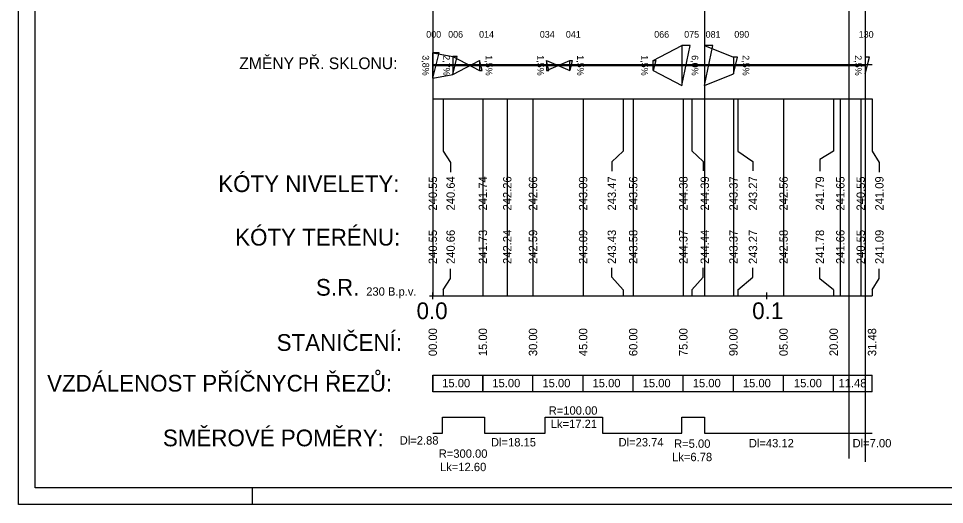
# Model space of a CAD drawing. Extents: x -598463 to -597973, y -1203201 to -1202904.
# Drawn here: x -598463.2 to -598186, y -1203201.3 to -1203056 of the extents above; entities that cross this region are included whole.
import ezdxf

# ---------------------------------------------------------------- set-up
doc = ezdxf.new("R2010")
doc.units = 0
for name, color, linetype in [('geom_osa_popis', 7, 'Continuous'), ('geom_Pomoc', 7, 'Continuous'), ('profil_popis', 7, 'Continuous'), ('profil_popis_klopeni', 7, 'Continuous'), ('profil_popis_navrh', 7, 'Continuous'), ('profil_popis_niveleta', 7, 'Continuous'), ('profil_popis_osy', 7, 'Continuous'), ('profil_popis_teren', 7, 'Continuous'), ('sil_ramecek', 7, 'Continuous')]:
    doc.layers.add(name, color=color, linetype=linetype)

msp = doc.modelspace()

# ---------------------------------------------------------------- linework, layer by layer
at = {"layer": 'geom_Pomoc'}
for p, q in [((-598339.21, -1202935.14), (-598339.21, -1203138.85)), ((-598214.71, -1202935.14), (-598214.71, -1203187.52)), ((-598257.88, -1202997.03), (-598257.88, -1203138.85)), ((-598209.75, -1203028.31), (-598209.75, -1203188.52)), ((-598339.21, -1203069.69), (-598207.73, -1203069.69)), ((-598339.21, -1203079.99), (-598207.73, -1203079.99))]:
    msp.add_line(p, q, dxfattribs=at)
at = {"layer": 'profil_popis'}
for p, q in [((-598336.05, -1203079.99), (-598336.05, -1203095.61)), ((-598316.92, -1203079.99), (-598316.92, -1203138.85)), ((-598282.26, -1203079.99), (-598282.26, -1203095.61)), ((-598261.63, -1203079.99), (-598261.63, -1203095.55)), ((-598247.91, -1203079.99), (-598247.91, -1203095.61)), ((-598217.22, -1203079.99), (-598217.22, -1203138.85)), ((-598211.12, -1203079.99), (-598211.12, -1203138.85)), ((-598336.05, -1203137.12), (-598336.05, -1203138.85)), ((-598282.26, -1203137.12), (-598282.26, -1203138.85)), ((-598261.63, -1203137.12), (-598261.63, -1203138.85)), ((-598247.91, -1203137.12), (-598247.91, -1203138.85)), ((-598339.21, -1203162.62), (-598339.21, -1203167.24)), ((-598324.21, -1203162.62), (-598324.21, -1203167.24))]:
    msp.add_line(p, q, dxfattribs=at)
for points in [[(-598339.21, -1203079.99), (-598339.21, -1203083.85), (-598339.21, -1203093.85), (-598339.21, -1203138.85)], [(-598324.21, -1203079.99), (-598324.21, -1203083.85), (-598324.21, -1203093.85), (-598324.21, -1203138.85)], [(-598309.21, -1203079.99), (-598309.21, -1203083.85), (-598309.21, -1203093.85), (-598309.21, -1203138.85)], [(-598294.21, -1203079.99), (-598294.21, -1203083.85), (-598294.21, -1203093.85), (-598294.21, -1203138.85)], [(-598279.21, -1203079.99), (-598279.21, -1203083.85), (-598279.21, -1203093.85), (-598279.21, -1203138.85)], [(-598264.21, -1203079.99), (-598264.21, -1203083.85), (-598264.21, -1203093.85), (-598264.21, -1203138.85)], [(-598249.21, -1203079.99), (-598249.21, -1203083.85), (-598249.21, -1203093.85), (-598249.21, -1203138.85)], [(-598234.21, -1203079.99), (-598234.21, -1203083.85), (-598234.21, -1203093.85), (-598234.21, -1203138.85)], [(-598219.21, -1203079.99), (-598219.21, -1203083.85), (-598219.21, -1203093.85), (-598219.21, -1203095.61)], [(-598207.73, -1203079.99), (-598207.73, -1203083.85), (-598207.73, -1203093.85), (-598207.73, -1203095.61)], [(-598336.05, -1203095.61), (-598333.86, -1203099.05), (-598333.86, -1203101.91)], [(-598282.26, -1203095.61), (-598285.62, -1203098.8), (-598285.62, -1203101.6)], [(-598261.63, -1203095.55), (-598258.28, -1203098.74), (-598258.28, -1203101.54)], [(-598247.91, -1203095.61), (-598243.37, -1203098.74), (-598243.37, -1203101.54)], [(-598219.21, -1203095.61), (-598223.33, -1203098.14), (-598223.33, -1203101.6)], [(-598207.73, -1203095.61), (-598205.54, -1203099.05), (-598205.54, -1203101.91)], [(-598336.05, -1203137.12), (-598333.86, -1203133.67), (-598333.86, -1203130.82)], [(-598282.26, -1203137.12), (-598285.62, -1203133.32), (-598285.62, -1203130.52)], [(-598261.63, -1203137.12), (-598258.28, -1203133.28), (-598258.28, -1203130.48)], [(-598247.91, -1203137.12), (-598243.37, -1203133.28), (-598243.37, -1203130.48)], [(-598219.21, -1203137.12), (-598223.33, -1203133.83), (-598223.33, -1203130.38)], [(-598207.73, -1203137.12), (-598205.54, -1203133.67), (-598205.54, -1203130.82)], [(-598219.21, -1203137.12), (-598219.21, -1203138.85)], [(-598207.73, -1203137.12), (-598207.73, -1203138.85)]]:
    msp.add_lwpolyline(points, dxfattribs=at)
at = {"layer": 'profil_popis_klopeni'}
for p, q in [((-598273.21, -1203068.49), (-598264.64, -1203063.99)), ((-598257.85, -1203063.99), (-598249.21, -1203067.49)), ((-598339.21, -1203066.19), (-598333.21, -1203067.29)), ((-598339.21, -1203073.79), (-598339.21, -1203066.19)), ((-598339.21, -1203069.99), (-598257.85, -1203069.99)), ((-598333.21, -1203072.69), (-598325.21, -1203068.49)), ((-598305.21, -1203068.49), (-598298.21, -1203071.49)), ((-598305.21, -1203071.49), (-598298.21, -1203068.49)), ((-598257.85, -1203069.99), (-598214.71, -1203069.99)), ((-598214.71, -1203069.99), (-598209.75, -1203069.99)), ((-598339.21, -1203073.79), (-598333.21, -1203072.69)), ((-598273.21, -1203071.49), (-598264.63, -1203075.99)), ((-598257.85, -1203075.99), (-598249.21, -1203072.49))]:
    msp.add_line(p, q, dxfattribs=at)
for points in [[(-598264.64, -1203063.99), (-598264.63, -1203075.99), (-598262.14, -1203063.99)], [(-598257.85, -1203063.99), (-598257.84, -1203075.99), (-598255.35, -1203063.99)], [(-598339.21, -1203066.19), (-598339.21, -1203073.79), (-598337.31, -1203066.19)], [(-598333.21, -1203067.29), (-598333.21, -1203072.69), (-598331.86, -1203067.29)], [(-598325.21, -1203068.49), (-598325.21, -1203071.49), (-598324.46, -1203071.49)], [(-598305.21, -1203068.49), (-598305.21, -1203071.49), (-598304.46, -1203071.49)], [(-598298.21, -1203071.49), (-598298.21, -1203068.49), (-598297.46, -1203068.49)], [(-598273.21, -1203071.49), (-598273.21, -1203068.49), (-598272.46, -1203068.49)], [(-598249.21, -1203067.49), (-598249.21, -1203072.49), (-598247.96, -1203067.49)], [(-598209.75, -1203067.49), (-598209.75, -1203072.49), (-598208.5, -1203067.49)]]:
    msp.add_lwpolyline(points, close=True, dxfattribs=at)
msp.add_lwpolyline([(-598333.21, -1203067.29), (-598325.21, -1203071.49), (-598325.21, -1203071.49)], dxfattribs=at)
at = {"layer": 'profil_popis_navrh'}
for points in [[(-598339.21, -1203179.98), (-598336.33, -1203179.98), (-598336.33, -1203175.18), (-598323.73, -1203175.18), (-598323.73, -1203179.98), (-598305.58, -1203179.98), (-598305.58, -1203175.18), (-598288.37, -1203175.18), (-598288.37, -1203179.98), (-598264.63, -1203179.98), (-598264.63, -1203175.18), (-598257.85, -1203175.18), (-598257.85, -1203179.98)], [(-598257.85, -1203179.98), (-598214.71, -1203179.98)], [(-598214.71, -1203179.98), (-598207.73, -1203179.98)]]:
    msp.add_lwpolyline(points, dxfattribs=at)
at = {"layer": 'profil_popis_osy'}
for p, q in [((-598340.21, -1203138.85), (-598338.21, -1203138.85)), ((-598339.21, -1203139.85), (-598339.21, -1203137.85)), ((-598339.21, -1203138.85), (-598207.73, -1203138.85)), ((-598239.21, -1203139.85), (-598239.21, -1203137.85))]:
    msp.add_line(p, q, dxfattribs=at)
at = {"layer": 'sil_ramecek'}
for p, q in [((-598339.21, -1203167.61), (-598339.21, -1203162.61)), ((-598339.21, -1203162.61), (-598207.73, -1203162.61)), ((-598324.21, -1203167.61), (-598324.21, -1203162.61)), ((-598309.21, -1203167.61), (-598309.21, -1203162.61)), ((-598294.21, -1203167.61), (-598294.21, -1203162.61)), ((-598279.21, -1203167.61), (-598279.21, -1203162.61)), ((-598264.21, -1203167.61), (-598264.21, -1203162.61)), ((-598249.21, -1203167.61), (-598249.21, -1203162.61)), ((-598234.21, -1203167.61), (-598234.21, -1203162.61)), ((-598219.21, -1203167.61), (-598219.21, -1203162.61)), ((-598207.73, -1203167.61), (-598207.73, -1203162.61)), ((-598207.73, -1203167.61), (-598339.21, -1203167.61)), ((-598393.21, -1203201.29), (-598393.21, -1203196.29))]:
    msp.add_line(p, q, dxfattribs=at)
for points in [[(-598463.21, -1202904.29), (-597973.21, -1202904.29), (-597973.21, -1203201.29), (-598463.21, -1203201.29)], [(-598458.21, -1202909.29), (-597978.21, -1202909.29), (-597978.21, -1203196.29), (-598458.21, -1203196.29)]]:
    msp.add_lwpolyline(points, close=True, dxfattribs=at)

# ---------------------------------------------------------------- texts
at = {"layer": 'geom_osa_popis'}
msp.add_text('-', height=0.0001, rotation=360, dxfattribs=at).set_placement((-598339.21, -1203138.85))
at = {"layer": 'profil_popis'}
for s, height, rotation, p in [(' KÓTY TERÉNU: ', 5, 360, (-598400.22, -1203123.85)), ('S.R.', 5, 360, (-598374.19, -1203138.85)), ('230 B.p.v.', 2.5, 360, (-598359.13, -1203138.85)), ('0.0', 5, 360, (-598344.06, -1203145.85)), ('0.1', 5, 360, (-598243.59, -1203145.85)), (' STANIČENÍ: ', 5, 360, (-598387.8, -1203155.35)), ('00.00', 2.5, 90, (-598337.96, -1203156.92)), ('15.00', 2.5, 90, (-598322.96, -1203156.92)), ('30.00', 2.5, 90, (-598307.96, -1203156.92)), ('45.00', 2.5, 90, (-598292.96, -1203156.92)), ('60.00', 2.5, 90, (-598277.96, -1203156.92)), ('75.00', 2.5, 90, (-598262.96, -1203156.92)), ('90.00', 2.5, 90, (-598247.96, -1203156.92)), ('05.00', 2.5, 90, (-598232.96, -1203156.92)), ('20.00', 2.5, 90, (-598217.96, -1203156.92)), ('31.48', 2.5, 90, (-598206.48, -1203156.93)), (' VZDÁLENOST PŘÍČNYCH ŘEZŮ: ', 5, 360, (-598456.51, -1203167.52)), ('15.00', 2.5, 360, (-598336.38, -1203166.24)), ('15.00', 2.5, 360, (-598321.38, -1203166.24)), ('15.00', 2.5, 360, (-598306.38, -1203166.24)), ('15.00', 2.5, 360, (-598291.38, -1203166.24)), ('15.00', 2.5, 360, (-598276.38, -1203166.24)), ('15.00', 2.5, 360, (-598261.38, -1203166.24)), ('15.00', 2.5, 360, (-598246.38, -1203166.24)), ('15.00', 2.5, 360, (-598231.09, -1203166.24)), ('11.48', 2.5, 360, (-598217.75, -1203166.24))]:
    msp.add_text(s, height=height, rotation=rotation, dxfattribs=at).set_placement(p)
at = {"layer": 'profil_popis_klopeni'}
for s, rotation, p in [('000', 360, (-598341.17, -1203061.7)), ('006', 360, (-598334.61, -1203061.7)), ('014', 360, (-598325.35, -1203061.7)), ('034', 360, (-598307.17, -1203061.7)), ('041', 360, (-598299.37, -1203061.7)), ('066', 360, (-598272.93, -1203061.7)), ('075', 360, (-598263.95, -1203061.7)), ('081', 360, (-598257.53, -1203061.7)), ('090', 360, (-598248.95, -1203061.7)), ('130', 360, (-598211.71, -1203061.7)), ('3,8%', 270, (-598342.3, -1203066.93)), ('2,7%', 270, (-598336.07, -1203066.93)), ('1,5%', 270, (-598323.38, -1203066.93)), ('1,5%', 270, (-598307.93, -1203066.93)), ('1,5%', 270, (-598296, -1203066.93)), ('1,5%', 270, (-598276.76, -1203066.93)), ('6,0%', 270, (-598261.72, -1203066.93)), ('2,5%', 270, (-598246.46, -1203066.93)), ('2,5%', 270, (-598212.83, -1203066.93))]:
    msp.add_text(s, height=2, rotation=rotation, dxfattribs=at).set_placement(p)
at = {"layer": 'profil_popis_navrh'}
for s, height, p in [('ZMĚNY PŘ. SKLONU: ', 3.5, (-598397.12, -1203071.09)), (' KÓTY NIVELETY: ', 5, (-598405.28, -1203107.85)), ('R=100.00', 2.5, (-598304.51, -1203174.43)), (' SMĚROVÉ POMĚRY: ', 5, (-598421.85, -1203183.89)), ('Lk=17.21', 2.5, (-598303.89, -1203178.43)), ('Dl=2.88', 2.5, (-598349.11, -1203183.38)), ('Dl=18.15', 2.5, (-598321.79, -1203183.93)), ('Dl=23.74', 2.5, (-598283.6, -1203183.93)), ('R=5.00', 2.5, (-598266.98, -1203184.34)), ('Dl=43.12', 2.5, (-598244.6, -1203184.21)), ('Dl=7.00', 2.5, (-598213.55, -1203184.21)), ('R=300.00', 2.5, (-598337.43, -1203187.32)), ('Lk=6.78', 2.5, (-598267.57, -1203188.34)), ('Lk=12.60', 2.5, (-598337.04, -1203191.32))]:
    msp.add_text(s, height=height, rotation=360, dxfattribs=at).set_placement(p)
at = {"layer": 'profil_popis_niveleta'}
for s, p in [('240.55', (-598337.96, -1203113.39)), ('240.64', (-598332.61, -1203113.36)), ('241.74', (-598322.96, -1203113.36)), ('242.26', (-598315.67, -1203113.37)), ('242.66', (-598307.96, -1203113.37)), ('243.09', (-598292.96, -1203113.37)), ('243.47', (-598284.37, -1203113.37)), ('243.56', (-598277.96, -1203113.37)), ('244.38', (-598262.96, -1203113.37)), ('244.39', (-598256.54, -1203113.37)), ('243.37', (-598247.96, -1203113.37)), ('243.27', (-598242.11, -1203113.37)), ('242.56', (-598232.96, -1203113.37)), ('241.79', (-598222.08, -1203113.37)), ('241.65', (-598215.97, -1203113.39)), ('240.55', (-598209.87, -1203113.39)), ('241.09', (-598204.27, -1203113.37))]:
    msp.add_text(s, height=2.5, rotation=90, dxfattribs=at).set_placement(p)
at = {"layer": 'profil_popis_teren'}
for s, p in [('240.55', (-598337.96, -1203129.39)), ('240.66', (-598332.61, -1203129.37)), ('241.73', (-598322.96, -1203129.37)), ('242.24', (-598315.67, -1203129.36)), ('242.59', (-598307.96, -1203129.37)), ('243.09', (-598292.96, -1203129.37)), ('243.43', (-598284.37, -1203129.37)), ('243.58', (-598277.96, -1203129.37)), ('244.37', (-598262.96, -1203129.37)), ('244.44', (-598256.54, -1203129.36)), ('243.37', (-598247.96, -1203129.37)), ('243.27', (-598242.11, -1203129.37)), ('242.58', (-598232.96, -1203129.37)), ('241.78', (-598222.08, -1203129.37)), ('241.66', (-598215.97, -1203129.37)), ('240.55', (-598209.87, -1203129.39)), ('241.09', (-598204.27, -1203129.37))]:
    msp.add_text(s, height=2.5, rotation=90, dxfattribs=at).set_placement(p)

doc.saveas('drawing.dxf')
